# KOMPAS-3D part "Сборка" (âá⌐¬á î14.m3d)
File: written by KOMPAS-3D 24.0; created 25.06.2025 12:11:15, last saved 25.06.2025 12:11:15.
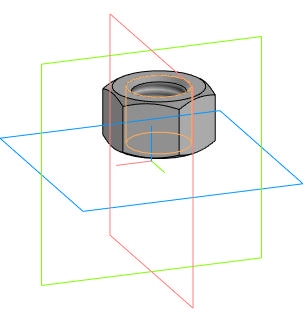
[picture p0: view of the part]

Document properties: Автор: PC321; Полное имя файла: C:\Для ноута\Инженерная графика\ППЭ 2025-2026\Варианты 1-38\Вариант 11 СБ\Вар 11 СБ\Гайка М14.m3d

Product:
- Component [standard]: Гайка М14-6H(S21) ГОСТ 5915-70  | qty 1  | pos. 1  | Масса: 0.02533; Раздел спецификации: Стандартные изделия; Рассекать на разрезах: no; additional columns: М14-6H (S21)
- Part/product: Сборка
    Масса: 0.02533

Referenced files in C:\Program Files\ASCON\KOMPAS-3D v21 Study\Libs\PARTLib\DATA\vault\Methods\Kompas\3D\: PLib_Nut_OST92_900.m3d
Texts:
  bcut1
  hole1
  hcut1
  hole2
  cut1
